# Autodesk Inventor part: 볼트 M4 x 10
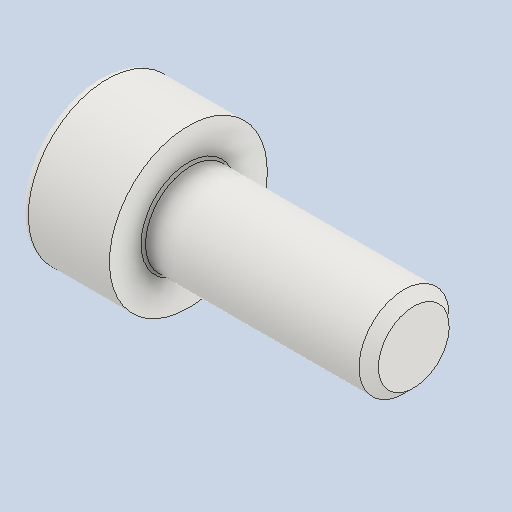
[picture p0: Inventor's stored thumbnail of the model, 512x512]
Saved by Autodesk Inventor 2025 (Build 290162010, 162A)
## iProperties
Created: 2024-07
Part Number: 볼트 M4 x 10
Material: 강철, 연강
Description: 6각머리 태핑 나사
Document SubType Name: Modeling
Designer: Admin
Density: 7.86 g/cm^3
Appearance: 기본값
Author: jhkim
Revision Number: 1
Sending System: Autodesk Inventor 2025
Preprocessor: ST-DEVELOPER v20
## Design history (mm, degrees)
feature "Solid1"
node "솔리드1"
